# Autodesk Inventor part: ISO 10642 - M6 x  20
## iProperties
Comments: To add or edit properties for Autodesk Inventor files, use iProperties.
Created: 2004-08
Part Number: ISO 10642 - M6 x  20
Vendor: Autodesk Inc.
Document SubType Name: Modeling
Designer: John Blackburn
Material: Default
Description: Hexagon Socket Countersunk Head Screw
Standard: ISO 10642
Alert: To add or edit properties for Autodesk Inventor files, use iProperties.
Control State: 0
Master: False
Checked Out: False
Shininess: 64.0
Length Units: 11269
Angle Units: 11279
Time Units: 11290
Mass Units: 11283
Length Display Precision: 3
Angle Display Precision: 2
Compacted: True
EGR: 1
Density: 0.0
Volumn: 0.0
Area: 0.0
PropertySet Name: Model Information
Author: John Blackburn
Revision Number: 8
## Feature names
1. Body [Revolution]
2. Slot [Extrusion]
3. Chamfer1
